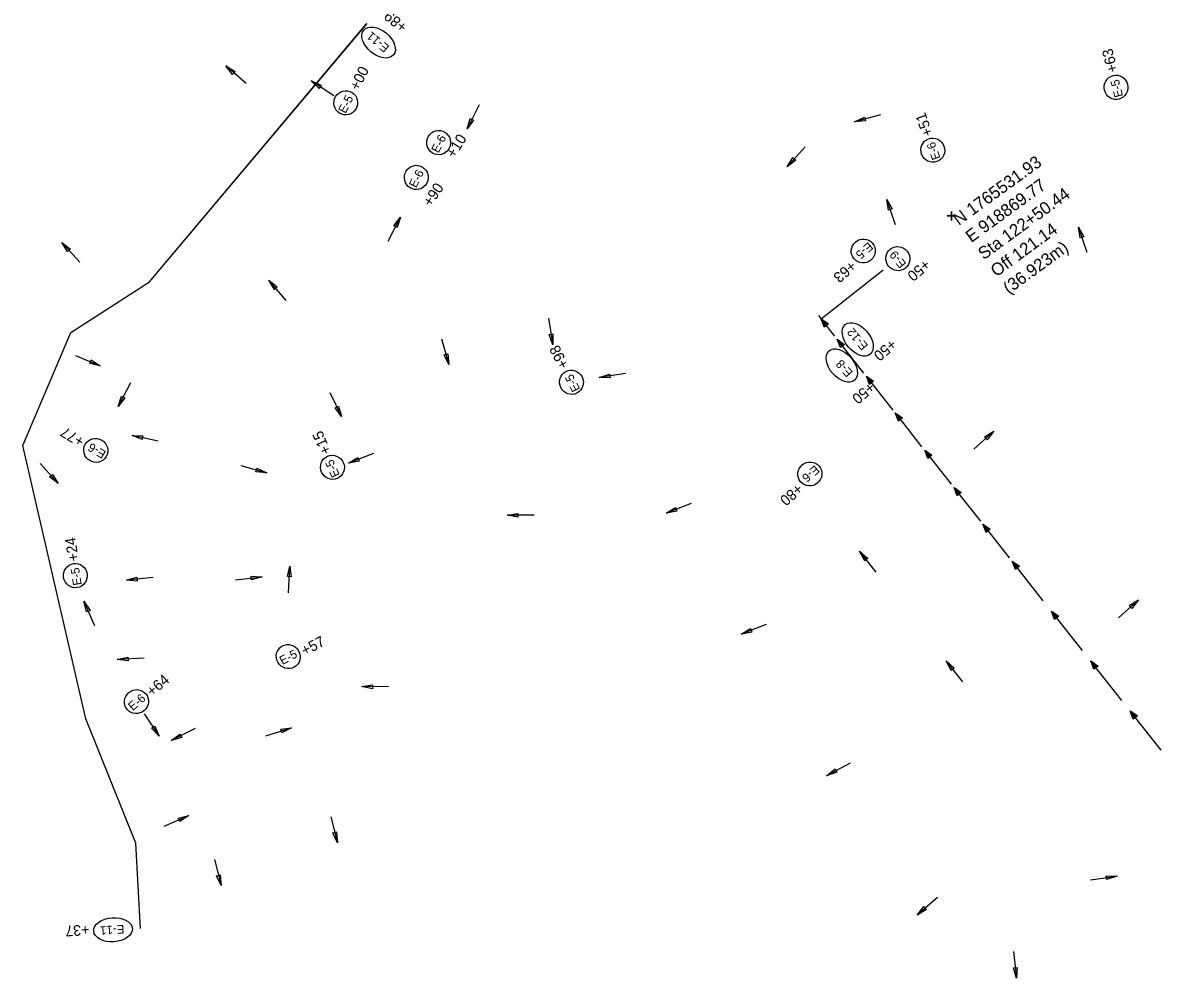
# Model space of a CAD drawing. Extents: x 918344 to 920005, y 1764082 to 1766125.
# Drawn here: x 918344 to 918988, y 1765101 to 1765641 of the extents above; entities that cross this region are included whole.
import ezdxf

# ---------------------------------------------------------------- set-up
doc = ezdxf.new("R2010")
doc.units = 0
for name, color, linetype in [('1', 7, 'Continuous'), ('43', 7, 'Continuous'), ('44', 7, 'Continuous'), ('EC_CG', 7, 'Continuous'), ('Level 1', 7, 'Continuous'), ('Level 8', 7, 'Continuous'), ('Plan Notes', 7, 'Continuous')]:
    doc.layers.add(name, color=color, linetype=linetype)

msp = doc.modelspace()

# ---------------------------------------------------------------- linework, layer by layer
at = {"layer": '1'}
for centre, major_axis, ratio in [((918839.41, 1765507.78), (4.3, -5.37), 0.97521), ((918816.73, 1765462.12), (-7.06, 8.38), 0.622952), ((918807.7, 1765447.34), (-7.2, 8.26), 0.622952)]:
    msp.add_ellipse(centre, major_axis=major_axis, ratio=ratio, dxfattribs=at)
at = {"layer": '43'}
for p, q in [((918459.23, 1765616.85), (918464.53, 1765613.69)), ((918463.13, 1765612.06), (918459.23, 1765616.85)), ((918464.53, 1765613.69), (918463.13, 1765612.06)), ((918595.75, 1765581.19), (918597.51, 1765587.1)), ((918599.43, 1765586.14), (918595.75, 1765581.19)), ((918597.51, 1765587.1), (918599.43, 1765586.14)), ((918814.9, 1765585.16), (918820.46, 1765587.82)), ((918821.04, 1765585.76), (918814.9, 1765585.16)), ((918820.46, 1765587.82), (918821.04, 1765585.76)), ((918776.8, 1765559.78), (918780.1, 1765564.98)), ((918780.1, 1765564.98), (918781.69, 1765563.53)), ((918781.69, 1765563.53), (918776.8, 1765559.78)), ((918833.19, 1765541.33), (918836.17, 1765535.92)), ((918834.14, 1765535.23), (918833.19, 1765541.33)), ((918836.17, 1765535.92), (918834.14, 1765535.23)), ((918554.32, 1765526.35), (918558.01, 1765531.3)), ((918556.24, 1765525.39), (918554.32, 1765526.35)), ((918558.01, 1765531.3), (918556.24, 1765525.39)), ((918941.56, 1765525.6), (918944.54, 1765520.2)), ((918942.51, 1765519.51), (918941.56, 1765525.6)), ((918944.54, 1765520.2), (918942.51, 1765519.51)), ((918366.48, 1765517.01), (918371.35, 1765513.23)), ((918369.76, 1765511.79), (918366.48, 1765517.01)), ((918371.35, 1765513.23), (918369.76, 1765511.79)), ((918483.6, 1765495.7), (918488.36, 1765491.78)), ((918486.73, 1765490.38), (918483.6, 1765495.7)), ((918488.36, 1765491.78), (918486.73, 1765490.38)), ((918642.22, 1765464.88), (918644.33, 1765465.23)), ((918644.26, 1765459.06), (918642.22, 1765464.88)), ((918644.33, 1765465.23), (918644.26, 1765459.06)), ((918382.25, 1765448.54), (918383.07, 1765450.52)), ((918388.27, 1765447.19), (918382.25, 1765448.54)), ((918383.07, 1765450.52), (918388.27, 1765447.19)), ((918582.75, 1765453.37), (918584.81, 1765453.97)), ((918585.47, 1765447.83), (918582.75, 1765453.37)), ((918584.81, 1765453.97), (918585.47, 1765447.83)), ((918670.51, 1765440.59), (918676.37, 1765442.53)), ((918676.37, 1765442.53), (918676.68, 1765440.41)), ((918676.68, 1765440.41), (918670.51, 1765440.59)), ((918398.32, 1765424.11), (918400.2, 1765429.99)), ((918400.2, 1765429.99), (918402.1, 1765428.99)), ((918402.1, 1765428.99), (918398.32, 1765424.11)), ((918521.13, 1765423.43), (918523.06, 1765424.36)), ((918524.72, 1765418.41), (918521.13, 1765423.43)), ((918523.06, 1765424.36), (918524.72, 1765418.41)), ((918888.49, 1765406.97), (918893.7, 1765410.27)), ((918893.7, 1765410.27), (918889.94, 1765405.38)), ((918406.21, 1765407.74), (918412.37, 1765407.49)), ((918411.91, 1765405.39), (918406.21, 1765407.74)), ((918412.37, 1765407.49), (918411.91, 1765405.39)), ((918889.94, 1765405.38), (918888.49, 1765406.97)), ((918528.67, 1765392.14), (918533.97, 1765395.29)), ((918534.73, 1765393.28), (918528.67, 1765392.14)), ((918533.97, 1765395.29), (918534.73, 1765393.28)), ((918359.57, 1765384.34), (918361.17, 1765385.77)), ((918364.41, 1765380.52), (918359.57, 1765384.34)), ((918361.17, 1765385.77), (918364.41, 1765380.52)), ((918476.27, 1765387.18), (918476.85, 1765389.24)), ((918482.41, 1765386.55), (918476.27, 1765387.18)), ((918476.85, 1765389.24), (918482.41, 1765386.55)), ((918708.27, 1765363.77), (918713.55, 1765366.95)), ((918714.32, 1765364.94), (918708.27, 1765363.77)), ((918713.55, 1765366.95), (918714.32, 1765364.94)), ((918618.42, 1765362.64), (918624.5, 1765363.7)), ((918624.49, 1765361.56), (918618.42, 1765362.64)), ((918624.5, 1765363.7), (918624.49, 1765361.56)), ((918817.8, 1765342.35), (918822.4, 1765338.24)), ((918820.72, 1765336.91), (918817.8, 1765342.35)), ((918494.07, 1765327.89), (918495.39, 1765333.91)), ((918495.39, 1765333.91), (918496.22, 1765327.8)), ((918822.4, 1765338.24), (918820.72, 1765336.91)), ((918403, 1765325.85), (918408.93, 1765327.54)), ((918408.93, 1765327.54), (918409.15, 1765325.4)), ((918473.87, 1765326.07), (918473.64, 1765328.21)), ((918473.64, 1765328.21), (918479.8, 1765327.78)), ((918479.8, 1765327.78), (918473.87, 1765326.07)), ((918496.22, 1765327.8), (918494.07, 1765327.89)), ((918409.15, 1765325.4), (918403, 1765325.85)), ((918378.97, 1765313.93), (918382.44, 1765308.83)), ((918380.49, 1765307.95), (918378.97, 1765313.93)), ((918970.27, 1765311.51), (918975.48, 1765314.81)), ((918975.48, 1765314.81), (918971.72, 1765309.92)), ((918382.44, 1765308.83), (918380.49, 1765307.95)), ((918971.72, 1765309.92), (918970.27, 1765311.51)), ((918750.79, 1765295.38), (918756.08, 1765298.56)), ((918756.85, 1765296.55), (918750.79, 1765295.38)), ((918756.08, 1765298.56), (918756.85, 1765296.55)), ((918397.85, 1765280.94), (918403.85, 1765282.37)), ((918403.85, 1765282.37), (918403.97, 1765280.23)), ((918403.97, 1765280.23), (918397.85, 1765280.94)), ((918866.73, 1765280.27), (918871.33, 1765276.16)), ((918869.64, 1765274.83), (918866.73, 1765280.27)), ((918871.33, 1765276.16), (918869.64, 1765274.83)), ((918536.1, 1765265.67), (918542.19, 1765266.66)), ((918542.16, 1765264.52), (918536.1, 1765265.67)), ((918542.19, 1765266.66), (918542.16, 1765264.52)), ((918417.24, 1765242.1), (918419.04, 1765243.27)), ((918419.04, 1765243.27), (918421.46, 1765237.6)), ((918421.46, 1765237.6), (918417.24, 1765242.1)), ((918428.38, 1765235.18), (918433.33, 1765238.87)), ((918434.29, 1765236.95), (918428.38, 1765235.18)), ((918433.33, 1765238.87), (918434.29, 1765236.95)), ((918490.33, 1765241.52), (918496.45, 1765242.31)), ((918490.97, 1765239.47), (918490.33, 1765241.52)), ((918496.45, 1765242.31), (918490.97, 1765239.47)), ((918799.12, 1765215.26), (918803.96, 1765219.08)), ((918804.98, 1765217.19), (918799.12, 1765215.26)), ((918803.96, 1765219.08), (918804.98, 1765217.19)), ((918432.36, 1765191.3), (918438.37, 1765192.71)), ((918433.21, 1765189.33), (918432.36, 1765191.3)), ((918438.37, 1765192.71), (918433.21, 1765189.33)), ((918519.83, 1765182.96), (918521.91, 1765183.48)), ((918522.34, 1765177.32), (918519.83, 1765182.96)), ((918521.91, 1765183.48), (918522.34, 1765177.32)), ((918454.05, 1765158.71), (918456.14, 1765159.23)), ((918456.14, 1765159.23), (918456.56, 1765153.08)), ((918957.62, 1765156.6), (918957.32, 1765158.73)), ((918957.32, 1765158.73), (918963.48, 1765158.51)), ((918456.56, 1765153.08), (918454.05, 1765158.71)), ((918963.48, 1765158.51), (918957.62, 1765156.6)), ((918850.26, 1765136.42), (918854.16, 1765141.2)), ((918855.56, 1765139.57), (918850.26, 1765136.42)), ((918854.16, 1765141.2), (918855.56, 1765139.57)), ((918904.79, 1765106.62), (918906.92, 1765106.86)), ((918906.56, 1765100.71), (918904.79, 1765106.62)), ((918906.92, 1765106.86), (918906.56, 1765100.71))]:
    msp.add_line(p, q, dxfattribs=at)
for points in [[(918470.73, 1765606.92), (918459.23, 1765616.85)], [(918602.54, 1765594.77), (918595.75, 1765581.19)], [(918829.53, 1765589.23), (918814.9, 1765585.16)], [(918787.05, 1765570.98), (918776.8, 1765559.78)], [(918838.1, 1765526.95), (918833.19, 1765541.33)], [(918551.18, 1765517.73), (918558.01, 1765531.3)], [(918946.47, 1765511.23), (918941.56, 1765525.6)], [(918376.67, 1765505.75), (918366.48, 1765517.01)], [(918493.47, 1765484.15), (918483.6, 1765495.7)], [(918641.8, 1765474.05), (918644.26, 1765459.06)], [(918581.24, 1765462.42), (918585.47, 1765447.83)], [(918374.25, 1765453.04), (918388.27, 1765447.19)], [(918685.54, 1765442.79), (918670.51, 1765440.59)], [(918405.39, 1765437.55), (918398.32, 1765424.11)], [(918518.17, 1765432.12), (918524.72, 1765418.41)], [(918882.48, 1765400.03), (918893.7, 1765410.27)], [(918421.05, 1765404.5), (918406.21, 1765407.74)], [(918542.87, 1765397.51), (918528.67, 1765392.14)], [(918354.3, 1765391.86), (918364.41, 1765380.52)], [(918467.79, 1765390.69), (918482.41, 1765386.55)], [(918722.45, 1765369.21), (918708.27, 1765363.77)], [(918633.61, 1765362.61), (918618.42, 1765362.64)], [(918827.2, 1765330.42), (918817.8, 1765342.35)], [(918494.78, 1765318.74), (918495.39, 1765333.91)], [(918418.1, 1765327.41), (918403, 1765325.85)], [(918464.69, 1765326.18), (918479.8, 1765327.78)], [(918385.21, 1765300.08), (918378.97, 1765313.93)], [(918964.26, 1765304.57), (918975.48, 1765314.81)], [(918764.97, 1765300.82), (918750.79, 1765295.38)], [(918413.01, 1765281.84), (918397.85, 1765280.94)], [(918876.13, 1765268.34), (918866.73, 1765280.27)], [(918551.28, 1765265.47), (918536.1, 1765265.67)], [(918413.15, 1765250.31), (918421.46, 1765237.6)], [(918441.95, 1765242), (918428.38, 1765235.18)], [(918481.95, 1765237.77), (918496.45, 1765242.31)], [(918812.49, 1765222.46), (918799.12, 1765215.26)], [(918424.42, 1765186.71), (918438.37, 1765192.71)], [(918518.66, 1765192.06), (918522.34, 1765177.32)], [(918452.89, 1765167.82), (918456.56, 1765153.08)], [(918948.44, 1765156.39), (918963.48, 1765158.51)], [(918861.77, 1765146.33), (918850.26, 1765136.42)], [(918904.79, 1765115.79), (918906.56, 1765100.71)]]:
    msp.add_lwpolyline(points, dxfattribs=at)
at = {"layer": 'EC_CG'}
for p, q in [((918416.04, 1765494.69), (918539.14, 1765640.9)), ((918416.04, 1765494.69), (918538.89, 1765640.61)), ((918507.61, 1765608.36), (918513.27, 1765605.89)), ((918512.08, 1765604.1), (918507.61, 1765608.36)), ((918513.27, 1765605.89), (918512.08, 1765604.1)), ((918371.53, 1765466.03), (918416.04, 1765494.69)), ((918371.53, 1765466.03), (918416.04, 1765494.69)), ((918344.4, 1765402.1), (918371.53, 1765466.03)), ((918344.4, 1765402.1), (918371.53, 1765466.03)), ((918380.02, 1765247.49), (918344.4, 1765402.1)), ((918380.02, 1765247.49), (918344.4, 1765402.1)), ((918408.44, 1765177.14), (918380.02, 1765247.49)), ((918408.44, 1765177.14), (918380.02, 1765247.49)), ((918411.04, 1765128.92), (918408.44, 1765177.14)), ((918411.04, 1765128.92), (918408.44, 1765177.14))]:
    msp.add_line(p, q, dxfattribs=at)
msp.add_lwpolyline([(918520.27, 1765599.95), (918507.61, 1765608.36)], dxfattribs=at)
for centre, major_axis, ratio in [((918545.7, 1765630.05), (-8.41, 7.02), 0.622952), ((918545.7, 1765630.05), (-8.41, 7.02), 0.622952), ((918527.12, 1765595.95), (-1.01, -6.81), 0.97521), ((918527.12, 1765595.95), (-1.01, -6.81), 0.97521), ((918579.63, 1765573.44), (-1.01, -6.81), 0.97521), ((918567, 1765553.73), (-1.01, -6.81), 0.97521), ((918654.79, 1765437.84), (3.1, -6.14), 0.97521), ((918654.79, 1765437.84), (3.1, -6.14), 0.97521), ((918385.68, 1765399.31), (5.92, -3.51), 0.97521), ((918374.14, 1765328.47), (1.05, -6.8), 0.97521), ((918374.14, 1765328.47), (1.05, -6.8), 0.97521), ((918494.57, 1765282.67), (4.48, -5.22), 0.97521), ((918408.7, 1765257.2), (-5.22, -4.48), 0.97521), ((918395.46, 1765128.12), (-10.93, -0.73), 0.622952), ((918395.46, 1765128.12), (-10.93, -0.73), 0.622952)]:
    msp.add_ellipse(centre, major_axis=major_axis, ratio=ratio, dxfattribs=at)
at = {"layer": 'Level 1'}
for centre, major_axis in [((918962.84, 1765604.71), (1.71, -6.67)), ((918859.18, 1765569.14), (2.37, -6.46)), ((918819.85, 1765512.11), (5.22, 4.48)), ((918519.57, 1765389.72), (2.8, -6.29)), ((918789.64, 1765385.98), (5.22, 4.48))]:
    msp.add_ellipse(centre, major_axis=major_axis, ratio=0.97521, dxfattribs=at)
at = {"layer": 'Level 8'}
for p, q in [((918796.03, 1765473.8), (918831.16, 1765501.5)), ((918797.16, 1765472.36), (918794.64, 1765475.55)), ((918798.11, 1765469.34), (918796.56, 1765472.64)), ((918798.4, 1765469.57), (918796.65, 1765472.68)), ((918798.69, 1765469.79), (918796.73, 1765472.73)), ((918799.27, 1765470.24), (918796.89, 1765472.85)), ((918799.56, 1765470.47), (918796.96, 1765472.92)), ((918799.85, 1765470.7), (918797.02, 1765473)), ((918807.24, 1765457.7), (918805.69, 1765461)), ((918807.53, 1765457.93), (918805.78, 1765461.05)), ((918807.82, 1765458.15), (918805.86, 1765461.1)), ((918808.4, 1765458.61), (918806.02, 1765461.22)), ((918808.69, 1765458.83), (918806.09, 1765461.28)), ((918808.98, 1765459.07), (918806.15, 1765461.36)), ((918823.67, 1765436.85), (918822.13, 1765440.15)), ((918823.97, 1765437.08), (918822.21, 1765440.19)), ((918824.25, 1765437.3), (918822.29, 1765440.25)), ((918824.83, 1765437.75), (918822.45, 1765440.36)), ((918825.12, 1765437.98), (918822.52, 1765440.43)), ((918825.42, 1765438.21), (918822.58, 1765440.51)), ((918840.05, 1765416.06), (918838.5, 1765419.37)), ((918840.34, 1765416.29), (918838.59, 1765419.41)), ((918840.63, 1765416.52), (918838.67, 1765419.46)), ((918841.21, 1765416.97), (918838.83, 1765419.58)), ((918841.5, 1765417.2), (918838.9, 1765419.65)), ((918841.8, 1765417.43), (918838.96, 1765419.72)), ((918856.68, 1765394.96), (918855.13, 1765398.27)), ((918856.97, 1765395.19), (918855.22, 1765398.31)), ((918857.26, 1765395.42), (918855.3, 1765398.36)), ((918857.84, 1765395.87), (918855.46, 1765398.48)), ((918858.13, 1765396.1), (918855.53, 1765398.55)), ((918858.42, 1765396.33), (918855.59, 1765398.62)), ((918873.27, 1765373.91), (918871.73, 1765377.21)), ((918873.57, 1765374.14), (918871.81, 1765377.25)), ((918873.85, 1765374.36), (918871.9, 1765377.31)), ((918874.43, 1765374.82), (918872.05, 1765377.42)), ((918874.72, 1765375.04), (918872.12, 1765377.49)), ((918875.02, 1765375.27), (918872.18, 1765377.57)), ((918889.6, 1765353.19), (918888.05, 1765356.5)), ((918889.89, 1765353.42), (918888.14, 1765356.54)), ((918890.18, 1765353.65), (918888.22, 1765356.59)), ((918890.76, 1765354.1), (918888.38, 1765356.71)), ((918891.05, 1765354.33), (918888.45, 1765356.78)), ((918891.34, 1765354.56), (918888.51, 1765356.85)), ((918906.18, 1765332.15), (918904.63, 1765335.46)), ((918906.47, 1765332.38), (918904.72, 1765335.5)), ((918906.76, 1765332.61), (918904.8, 1765335.55)), ((918907.34, 1765333.06), (918904.96, 1765335.67)), ((918907.63, 1765333.29), (918905.03, 1765335.74)), ((918907.92, 1765333.52), (918905.09, 1765335.81)), ((918928.41, 1765303.94), (918926.86, 1765307.24)), ((918928.7, 1765304.17), (918926.95, 1765307.29)), ((918928.99, 1765304.39), (918927.03, 1765307.34)), ((918929.57, 1765304.85), (918927.19, 1765307.46)), ((918929.86, 1765305.08), (918927.26, 1765307.53)), ((918930.16, 1765305.31), (918927.32, 1765307.6)), ((918950.64, 1765275.73), (918949.1, 1765279.03)), ((918950.94, 1765275.96), (918949.18, 1765279.08)), ((918951.22, 1765276.18), (918949.27, 1765279.13)), ((918951.81, 1765276.64), (918949.42, 1765279.25)), ((918952.1, 1765276.86), (918949.49, 1765279.31)), ((918952.39, 1765277.1), (918949.56, 1765279.39)), ((918972.88, 1765247.52), (918971.33, 1765250.82)), ((918973.17, 1765247.75), (918971.42, 1765250.86)), ((918973.46, 1765247.97), (918971.5, 1765250.92)), ((918974.04, 1765248.43), (918971.66, 1765251.03)), ((918974.33, 1765248.65), (918971.73, 1765251.1)), ((918974.62, 1765248.88), (918971.79, 1765251.18))]:
    msp.add_line(p, q, dxfattribs=at)
for points in [[(918796.02, 1765473.8), (918800.15, 1765470.93), (918797.81, 1765469.11)], [(918805.15, 1765462.16), (918809.28, 1765459.29), (918806.94, 1765457.47)], [(918821.59, 1765441.31), (918825.71, 1765438.44), (918823.38, 1765436.62)], [(918837.97, 1765420.53), (918842.09, 1765417.66), (918839.76, 1765415.83)], [(918854.59, 1765399.43), (918858.72, 1765396.56), (918856.38, 1765394.73)], [(918871.19, 1765378.37), (918875.31, 1765375.5), (918872.98, 1765373.68)], [(918887.51, 1765357.66), (918891.64, 1765354.79), (918889.3, 1765352.96)], [(918904.09, 1765336.62), (918908.22, 1765333.75), (918905.88, 1765331.93)], [(918926.33, 1765308.41), (918930.45, 1765305.53), (918928.12, 1765303.71)], [(918948.56, 1765280.19), (918952.68, 1765277.32), (918950.35, 1765275.5)], [(918970.79, 1765251.98), (918974.92, 1765249.11), (918972.58, 1765247.29)]]:
    msp.add_lwpolyline(points, close=True, dxfattribs=at)
for points in [[(918803.72, 1765464.03), (918800.81, 1765467.72), (918796.04, 1765473.78)], [(918820.24, 1765443.01), (918809.94, 1765456.09), (918805.17, 1765462.14)], [(918836.68, 1765422.16), (918826.38, 1765435.23), (918821.61, 1765441.29)], [(918853.06, 1765401.38), (918842.76, 1765414.45), (918837.98, 1765420.5)], [(918869.69, 1765380.28), (918859.38, 1765393.35), (918854.61, 1765399.4)], [(918886.28, 1765359.22), (918875.98, 1765372.29), (918871.21, 1765378.35)], [(918902.6, 1765338.51), (918892.3, 1765351.58), (918887.53, 1765357.63)], [(918921.7, 1765314.27), (918908.88, 1765330.54), (918904.11, 1765336.59)], [(918943.94, 1765286.06), (918931.12, 1765302.33), (918926.34, 1765308.38)], [(918966.17, 1765257.85), (918953.35, 1765274.12), (918948.58, 1765280.17)], [(918988.4, 1765229.64), (918975.58, 1765245.9), (918970.81, 1765251.96)]]:
    msp.add_lwpolyline(points, dxfattribs=at)
at = {"layer": 'Plan Notes'}
msp.add_lwpolyline([(918869.77, 1765531.93), (918869.77, 1765534.43), (918869.77, 1765531.93), (918867.27, 1765531.93), (918869.77, 1765531.93), (918869.77, 1765529.43), (918869.77, 1765531.93), (918872.27, 1765531.93)], dxfattribs=at)

# ---------------------------------------------------------------- texts
at = {"layer": '1'}
for s, rotation, p in [('E-9 ', 128.65966, (918844.45, 1765504.88)), ('E-12', 130.14381, (918822.87, 1765458.58)), ('E-8 ', 131.04792, (918814.27, 1765443.46))]:
    msp.add_text(s, height=4.876, rotation=rotation, dxfattribs=at).set_placement(p)
at = {"layer": '44'}
for s, rotation, p in [('+63', 104.33325, (918963.97, 1765613.9)), ('+51', 110.10138, (918859.44, 1765578.18)), ('+63', 220.58924, (918812.74, 1765507.07)), ('+50', 219.76775, (918854.69, 1765507.82)), ('+50', 219.72636, (918835.64, 1765462.71)), ('+50', 219.72636, (918823.43, 1765438.37)), ('+15', 113.94605, (918519, 1765398.55)), ('+80', 220.58924, (918782.53, 1765380.94))]:
    msp.add_text(s, height=6, rotation=rotation, dxfattribs=at).set_placement(p)
at = {"layer": 'EC_CG'}
for s, height, rotation, p in [('+89', 6, 140.14208, (918562.45, 1765639.81)), ('E-11 ', 4.876, 140.14415, (918552.14, 1765627.8)), ('E-11 ', 4.876, 140.14415, (918552.14, 1765627.8)), ('+00', 6, 63.27481, (918534.3, 1765602.42)), ('+00', 6, 63.27481, (918534.3, 1765602.42)), ('E-5', 4.876, 63.33283, (918527, 1765589.61)), ('E-5', 4.876, 63.33283, (918527, 1765589.61)), ('E-6', 4.876, 63.33283, (918579.58, 1765567.22)), ('+10', 6, 58.08702, (918588.58, 1765564.29)), ('E-6', 4.876, 63.33283, (918566.94, 1765547.51)), ('+90', 6, 55.83201, (918575.2, 1765536.74)), ('+98', 6, 116.73403, (918653.49, 1765447.34)), ('E-5', 4.876, 116.79206, (918659.81, 1765433.94)), ('E-5', 4.876, 116.79206, (918659.81, 1765433.94)), ('+77', 6, 149.27639, (918379.82, 1765406.02)), ('E-6', 4.876, 149.33441, (918391.9, 1765398.58)), ('+24', 6, 98.69716, (918376.14, 1765337)), ('+24', 6, 98.69716, (918376.14, 1765337)), ('E-5', 4.876, 98.75518, (918377.75, 1765323.32)), ('E-5', 4.876, 98.75518, (918377.75, 1765323.32)), ('+57', 6, 27.67586, (918503.83, 1765282.97)), ('E-5', 4.876, 27.73388, (918491.21, 1765277.86)), ('+64', 6, 40.58924, (918417.54, 1765259.78)), ('E-6', 4.876, 40.64727, (918406.59, 1765251.77)), ('+37', 6, 183.79865, (918381.87, 1765131.19)), ('+37', 6, 183.79865, (918381.87, 1765131.19)), ('E-11 ', 4.876, 183.80071, (918401.68, 1765130.94)), ('E-11 ', 4.876, 183.80071, (918401.68, 1765130.94))]:
    msp.add_text(s, height=height, rotation=rotation, dxfattribs=at).set_placement(p)
at = {"layer": 'Level 1'}
for s, rotation, p in [('E-5', 104.39128, (918966.86, 1765599.75)), ('E-6', 110.1594, (918863.62, 1765564.74)), ('E-5', 220.64727, (918822.79, 1765517.45)), ('E-5', 114.00407, (918523.84, 1765385.38)), ('E-6', 220.64727, (918792.48, 1765391.22))]:
    msp.add_text(s, height=4.876, rotation=rotation, dxfattribs=at).set_placement(p)
at = {"layer": 'Plan Notes'}
for s, p in [('N 1765531.93  ', (918873.89, 1765526.28)), ('E 918869.77  ', (918880.96, 1765516.58)), ('Sta 122+50.44 ', (918888.02, 1765506.88)), ('Off 121.14 ', (918895.09, 1765497.18)), ('(36.923m) ', (918902.15, 1765487.48))]:
    msp.add_text(s, height=7, rotation=36.06634, dxfattribs=at).set_placement(p)

doc.saveas('drawing.dxf')
